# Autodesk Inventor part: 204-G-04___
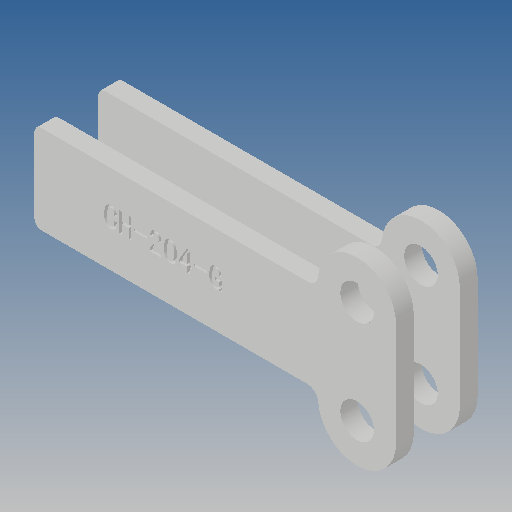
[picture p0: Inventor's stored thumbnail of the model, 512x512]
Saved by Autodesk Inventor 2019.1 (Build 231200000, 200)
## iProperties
Created: 2010-06
Part Number: 204-G-04___
Material: Ogólny
Document SubType Name: Modeling
Designer: CADENGINEERING4
Density: 1 g/cm^3
Appearance: Domyślna
Author: CADENGINEERING4
Revision Number: ANY
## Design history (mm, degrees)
feature "NONE"
feature "NONE:1"
node "Bryła1"
node "Bryła2"
